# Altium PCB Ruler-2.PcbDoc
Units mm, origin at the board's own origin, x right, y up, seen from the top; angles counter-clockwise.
Board outline 100.08 x 35.05 mm, 2 copper layers (Top Layer, Bottom Layer); 25 components, 0 nets, 858 pads, 0 vias.
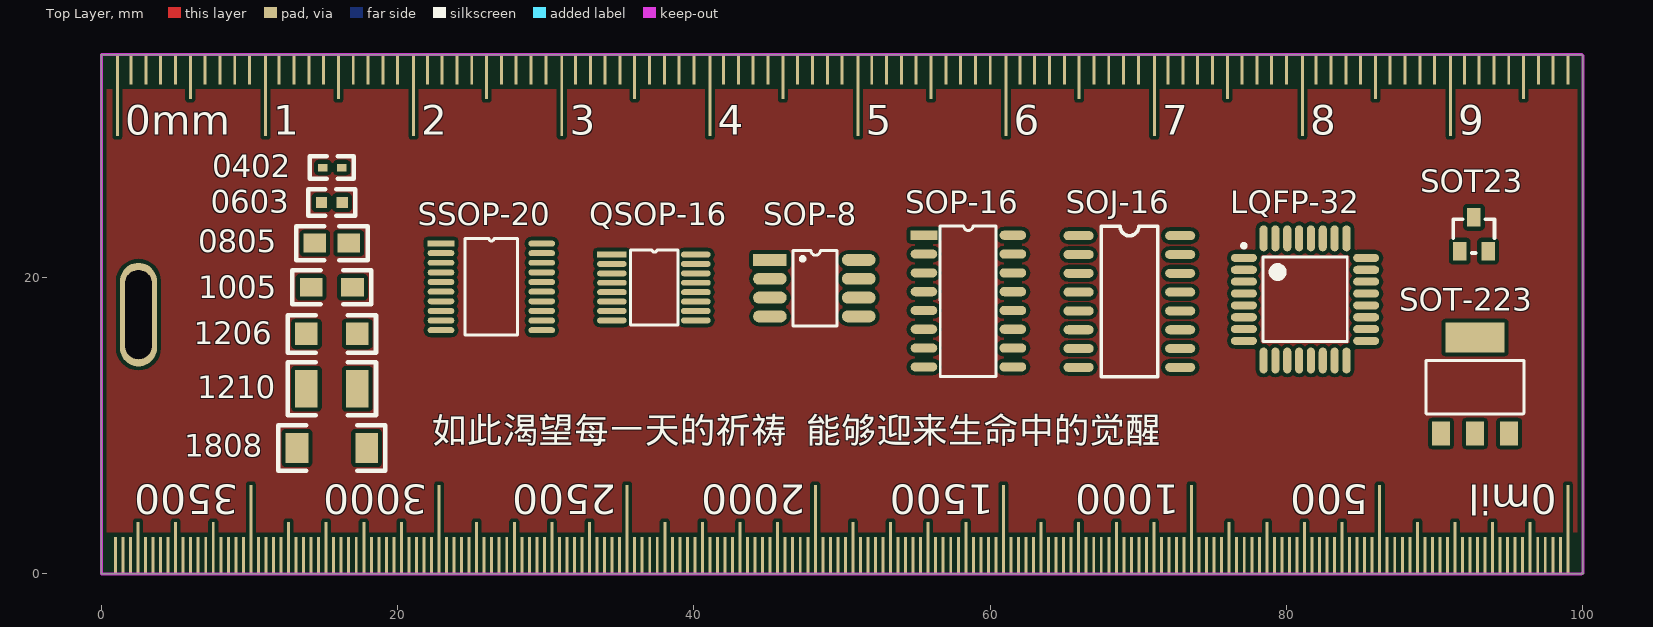
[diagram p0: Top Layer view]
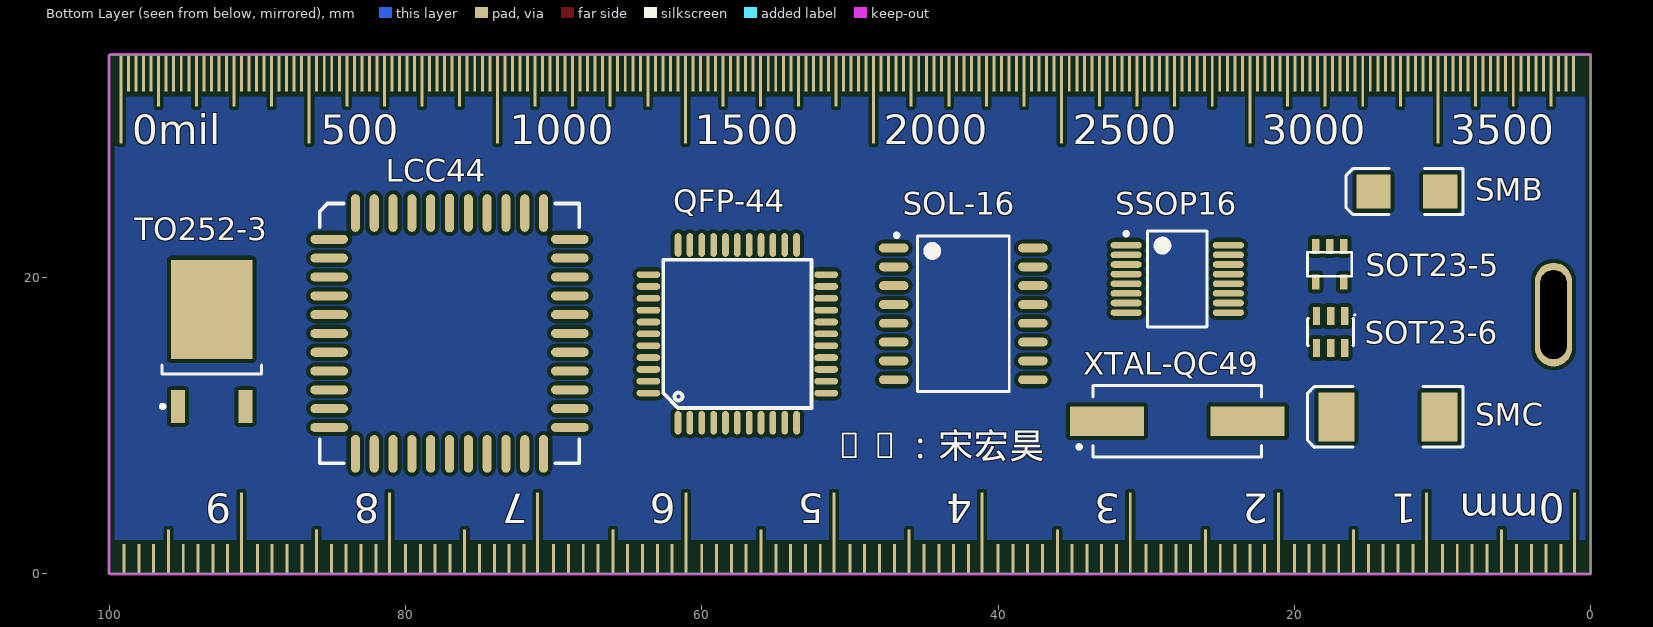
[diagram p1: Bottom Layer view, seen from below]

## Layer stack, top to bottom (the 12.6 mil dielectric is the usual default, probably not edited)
Top Solder: solder mask 0.0102, Solder Resist, Dk 3.5
Top Layer: signal copper 0.0356
Dielectric 1: dielectric 0.32, FR-4, Dk 4.8
Bottom Layer: signal copper 0.0356
Bottom Solder: solder mask 0.0102, Solder Resist, Dk 3.5

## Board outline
0,0 0,35.052 99.948,35.052 100,35 100,0.076 100.076,0

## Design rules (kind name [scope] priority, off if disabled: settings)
Clearance Clearance_1 [InPolygon] p1: gap=0.254 ignorepadtopadclearanceinfootprint=FALSE
Clearance [All] p2: gap=0.254 ignorepadtopadclearanceinfootprint=FALSE except(0: Arc-Hole Track-Hole SMDPad-Hole THPad-Hole Via-Hole Fill-Hole Poly-Hole Region-Hole Text-Hole)
PolygonConnect [All] p1: connectstyle=Relief reliefconductorwidth=0.254 reliefentries=4 polygonreliefangle="90 Angle" airgapwidth=0.254
RoutingVias [All] p1: holewidth=0.711 width=1.27 viastyle="Through Hole" minholewidth=0.711 minwidth=1.27 maxholewidth=0.711 maxwidth=1.27
SolderMaskExpansion [All] p1: expansion=0.102
Width [All] p1: maxlimit=0.254 minlimit=0.254 preferedwidth=0.254
30 further rules are at their usual default settings.

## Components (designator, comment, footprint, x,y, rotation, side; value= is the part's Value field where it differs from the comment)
0402 "0402" 0402 14.954,27.425 r0 top
0603 "0603" 0603 14.852,25.075 r0 top
0805 "0805" 0805 14.407,22.325 r0 top
1005 "1005" 1005 14.153,19.35 r0 top
1206 "1206" 1206 13.836,16.2 r0 top
1210 "1210" 1210 13.836,12.5 r0 top
1808 "1808" 1808 13.201,8.5 r0 top
LCC44 "LCC44" LCC44 77.028,24.358 r180 bottom
LQFP-32 "LQFP-32" LQFP-32 81.249,18.524 r0 top
QFP-44 "QFP-44" QFP-44 57.6,16.2 r180 bottom
QSOP-16 "QSOP-16" QSOP-16 34.46,21.554 r0 top
SMB "SMB" SMB 12.4,25.8 r0 bottom
SMC "SMC" SMC 13.675,10.6 r0 bottom
SOJ-16 "SOJ-16" SOJ-16 65.966,22.829 r0 top
SOL-16 "SOL-16" SOL-16_L 42.342,17.551 r180 bottom
SOP-8 "SOP-8" SOIC-8 45.124,21.189 r0 top
SOP-16 "SOP-16" SOP-16 55.524,22.859 r0 top
SOT23 "SOT23" SOT23 92.65,22.925 r0 top
SOT23-5 "SOT23-5" SOT23-5 16.661,22.1 r180 bottom
SOT23-6 "SOT23-6" SOT23-6 17.55,16.325 r180 bottom
SOT-223 "SOT-223" SOT-223 92.725,9.475 r0 top
SSOP16 "SSOP16" SSOP16_N 27.9,19.91 r180 bottom
SSOP-20 "SSOP-20" SSOP-20 22.924,22.299 r0 top
TO252-3 "TO252-3" TO-252AA_M 93.08,15.7 r90 bottom
XTAL-QC49 "XTAL-QC49" XTAL-QC49/SMD 27.9,10.3 r180 bottom

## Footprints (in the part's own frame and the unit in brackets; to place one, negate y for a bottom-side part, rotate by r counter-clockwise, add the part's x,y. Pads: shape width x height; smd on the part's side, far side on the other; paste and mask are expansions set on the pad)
0402 [mil]
  rect 25x20 smd: 1(0,0) 2(50,0)
  silkscreen extent -35,-30 82,30
0603 [mil]
  rect 30x30 smd: 1(0,0) 2(55,0)
  silkscreen extent -35,-35 90,35
0805 [mil]
  rect 60x50 smd: 1(0,0) 2(90,0)
  silkscreen extent -50,-45 140,45
1005 [mil]
  rect 60x50 smd: 1(0,0) 2(110,0)
  silkscreen extent -50,-45 160,45
1206 [mil]
  rect 60x60 smd: 1(0,0) 2(135,0)
  silkscreen extent -50,-50 185,50
1210 [mil]
  rect 60x100 smd: 1(0,0) 2(135,0)
  silkscreen extent -50,-70 185,70
1808 [mil]
  rect 60x80 smd: 1(0,0) 2(185,0)
  silkscreen extent -50,-60 235,60
LCC44 [mil]
  oct 24x100 smd: 1(0,0)
  oval 24x100 smd: 2(-50,0) 3(-100,0) 4(-150,0) 5(-200,0) 6(-250,0) 18(-250,-640) 19(-200,-640) 20(-150,-640) 21(-100,-640) 22(-50,-640) 23(0,-640) 24(50,-640) 25(100,-640) 26(150,-640) 27(200,-640) 28(250,-640) 40(250,0) 41(200,0) 42(150,0) 43(100,0) 44(50,0)
  oval 100x24 smd: 7(-320,-70) 8(-320,-120) 9(-320,-170) 10(-320,-220) 11(-320,-270) 12(-320,-320) 13(-320,-370) 14(-320,-420) 15(-320,-470) 16(-320,-520) 17(-320,-570) 29(320,-570) 30(320,-520) 31(320,-470) 32(320,-420) 33(320,-370) 34(320,-320) 35(320,-270) 36(320,-220) 37(320,-170) 38(320,-120) 39(320,-70)
  silkscreen extent -345,-665 345,25
LQFP-32 [mm] "TQFP, 32-Leads, Body 9.2x9.2mm (max), Pitch 0.80mm, IPC Medium Density"
  oval 1.75x0.55 smd: 1(-4.125,2.8) 2(-4.125,2) 3(-4.125,1.2) 4(-4.125,0.4) 5(-4.125,-0.4) 6(-4.125,-1.2) 7(-4.125,-2) 8(-4.125,-2.8) 17(4.125,-2.8) 18(4.125,-2) 19(4.125,-1.2) 20(4.125,-0.4) 21(4.125,0.4) 22(4.125,1.2) 23(4.125,2) 24(4.125,2.8)
  oval 0.55x1.75 smd: 9(-2.8,-4.125) 10(-2,-4.125) 11(-1.2,-4.125) 12(-0.4,-4.125) 13(0.4,-4.125) 14(1.2,-4.125) 15(2,-4.125) 16(2.8,-4.125) 25(2.8,4.125) 26(2,4.125) 27(1.2,4.125) 28(0.4,4.125) 29(-0.4,4.125) 30(-1.2,4.125) 31(-2,4.125) 32(-2.8,4.125)
  silkscreen extent -4.25,-2.85 2.85,3.75, body extent -3.5,-3.5 3.5,3.5, height 1.6
QFP-44 [mm]
  oval 0.45x1.6 smd: 1(-4,-6) 2(-3.2,-6) 3(-2.4,-6) 4(-1.6,-6) 5(-0.8,-6) 6(0,-6) 7(0.8,-6) 8(1.6,-6) 9(2.4,-6) 10(3.2,-6) 11(4,-6) 23(4,6) 24(3.2,6) 25(2.4,6) 26(1.6,6) 27(0.8,6) 28(0,6) 29(-0.8,6) 30(-1.6,6) 31(-2.4,6) 32(-3.2,6) 33(-4,6)
  oval 1.6x0.45 smd: 12(6,-4) 13(6,-3.2) 14(6,-2.4) 15(6,-1.6) 16(6,-0.8) 17(6,0) 18(6,0.8) 19(6,1.6) 20(6,2.4) 21(6,3.2) 22(6,4) 34(-6,4) 35(-6,3.2) 36(-6,2.4) 37(-6,1.6) 38(-6,0.8) 39(-6,0) 40(-6,-0.8) 41(-6,-1.6) 42(-6,-2.4) 43(-6,-3.2) 44(-6,-4)
  silkscreen extent -5,-5 5,5, body extent -6.01,-6 5.99,6, height 1.1
QSOP-16 [mm]
  rect 2x0.4 smd: 1(0,0)
  oval 2x0.4 smd: 2(0,-0.635) 3(0,-1.27) 4(0,-1.905) 5(0,-2.54) 6(0,-3.175) 7(0,-3.81) 8(0,-4.445) 9(5.664,-4.445) 10(5.664,-3.81) 11(5.664,-3.175) 12(5.664,-2.54) 13(5.664,-1.905) 14(5.664,-1.27) 15(5.664,-0.635) 16(5.664,0)
  silkscreen extent 1.25,-4.76 4.46,0.32
SMB [mm] "DO-214-AA/SMB; 2 C-Bend Leads; Body 5.3 x 3.6 mm, inc. leads (LxW)"
  rect 2.3x2.3 smd: 1(-2.25,0) 2(2.25,0)
  silkscreen extent -3.8,-1.55 4.1,1.55
SMC [mm] "DO-214-AB/SMC; 2 C-Bend Leads; Body 7.9 x 5.9 mm, inc. leads (LxW)"
  rect 2.4x3.3 smd: 1(-3.475,0) 2(3.475,0)
  silkscreen extent -5.07,-2.05 5.43,2.05
SOIC-8 [mm]
  rect 2.27x0.8 smd: 1(0,0)
  oval 2.27x0.8 smd: 2(0,-1.27) 3(0,-2.54) 4(0,-3.81) 5(6,-3.81) 6(6,-2.54) 7(6,-1.27) 8(6,0)
  silkscreen extent 1.55,-4.44 4.54,0.64
SOJ-16 [mil]
  oval 80x24 smd: 1(0,0) 2(0,-50) 3(0,-100) 4(0,-150) 5(0,-200) 6(0,-250) 7(0,-300) 8(0,-350) 9(270,-350) 10(270,-300) 11(270,-250) 12(270,-200) 13(270,-150) 14(270,-100) 15(270,-50) 16(270,0)
  silkscreen extent 60,-375 210,25
SOL-16_L [mm] "16-Pin Small Outline Integrated Circuit 1.27 mm Pitch, IPC High Density"
  oval 2x0.6 smd: 1(-4.7,4.445) 2(-4.7,3.175) 3(-4.7,1.905) 4(-4.7,0.635) 5(-4.7,-0.635) 6(-4.7,-1.905) 7(-4.7,-3.175) 8(-4.7,-4.445) 9(4.7,-4.445) 10(4.7,-3.175) 11(4.7,-1.905) 12(4.7,-0.635) 13(4.7,0.635) 14(4.7,1.905) 15(4.7,3.175) 16(4.7,4.445)
  silkscreen extent -4.62,-5.25 3.1,5.42, body extent -5.18,-5.14 5.12,5.16, height 2.65
SOP-16 [mm]
  rect 1.8x0.62 smd: 1(0,0)
  oval 1.8x0.62 smd: 2(0,-1.27) 3(0,-2.54) 4(0,-3.81) 5(0,-5.08) 6(0,-6.35) 7(0,-7.62) 8(0,-8.89) 9(6,-8.89) 10(6,-7.62) 11(6,-6.35) 12(6,-5.08) 13(6,-3.81) 14(6,-2.54) 15(6,-1.27) 16(6,0)
  silkscreen extent 1.09,-9.53 4.88,0.64
SOT23 [mil]
  rect 36x50 smd: B(-37.5,-45) C(0,45) E(37.5,-45)
  silkscreen extent -55,-50 55,40, body extent -57,-47 57,50, height 39
SOT23-5 [mm]
  rect 0.5x1 smd: 1(0,0) 2(-0.95,0) 3(-1.9,0) 4(-1.9,-2.4) 5(0,-2.4)
  silkscreen extent -2.45,-2 0.55,-0.4, body extent -2.4,-2.6 0.5,0.2, height 1.09
SOT23-6 [mm] "SOT-23/SC-74A; 5 Leads; Body 3.1 x 3 mm, inc. leads (LxW max)"
  rect 0.5x1.2 smd: 1(0.95,1.075) 2(0,1.075) 3(-0.95,1.075) 4(-0.95,-1.075) 5(0,-1.075) 6(0.95,-1.075)
  silkscreen extent -1.55,-0.9 1.65,1.15, body extent -1.4,-1.19 1.4,1.23, height 1.08
SOT-223 [mm]
  rect 1.2x1.6 smd: 1(-2.3,0) 2(0,0) 3(2.3,0)
  rect 4x2 smd: 4(0,6.477)
  silkscreen extent -3.3,1.32 3.3,4.93
SSOP16_N [mm] "SOP, 16-Leads, Body 6.2x5.3mm, Pitch 0.65mm, IPC Medium Density"
  oval 2.1x0.45 smd: 1(-3.45,2.275) 2(-3.45,1.625) 3(-3.45,0.975) 4(-3.45,0.325) 5(-3.45,-0.325) 6(-3.45,-0.975) 7(-3.45,-1.625) 8(-3.45,-2.275) 9(3.45,-2.275) 10(3.45,-1.625) 11(3.45,-0.975) 12(3.45,-0.325) 13(3.45,0.325) 14(3.45,0.975) 15(3.45,1.625) 16(3.45,2.275)
  silkscreen extent -3.57,-3.25 2,3.25, body extent -2.7,-3.25 2.7,3.25, height 2
SSOP-20 [mm]
  rect 1.8x0.4 smd: 1(0,0)
  oval 1.8x0.4 smd: 2(0,-0.65) 3(0,-1.3) 4(0,-1.95) 5(0,-2.6) 6(0,-3.25) 7(0,-3.9) 8(0,-4.55) 9(0,-5.2) 10(0,-5.85) 11(6.8,-5.85) 12(6.8,-5.2) 13(6.8,-4.55) 14(6.8,-3.9) 15(6.8,-3.25) 16(6.8,-2.6) 17(6.8,-1.95) 18(6.8,-1.3) 19(6.8,-0.65) 20(6.8,0)
  silkscreen extent 1.63,-6.18 5.16,0.32
TO-252AA_M [mm] "D-PAK, 4-Leads, Body 6.1x6.5mm, Pitch 2.28mm, Lead Span 9.8mm, IPC Low Density"
  rect 2.2x0.95 smd: 1(-4.4,2.28) 3(-4.4,-2.28)
  rect 6.7x5.5 smd: 4(2.15,0)
  silkscreen extent -4.52,-3.35 -1.6,3.43, body extent -4.9,-3.27 5.04,3.27, height 2.39
XTAL-QC49/SMD [mm]
  rect 5x2 smd: 1(-4.75,0) 2(4.75,0)
  silkscreen extent -6.75,-2.4 5.7,2.4, body extent -6.7,-2.46 6.7,2.44, height 4

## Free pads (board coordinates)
  oval 2.5x7 hole 1.8 slot 6 at 90 deg: 0(2.5,17.5)
  rect 0.2x5.5 smd far side: 1(1.075,2.752) 11(11.075,2.752) 21(21.075,2.752) 31(31.075,2.752) 41(41.075,2.752) 51(51.075,2.752) 61(61.075,2.752) 71(71.075,2.752) 81(81.075,2.752) 91(91.075,2.752)
  rect 0.2x5.5 smd: 1(1.075,32.3) 11(11.075,32.3) 21(21.075,32.3) 31(31.075,32.3) 41(41.075,32.3) 51(51.075,32.3) 61(61.075,32.3) 71(71.075,32.3) 81(81.075,32.3) 91(91.075,32.3)
  rect 0.2x2 smd far side: 2(2,1.002) 3(3,1.002) 4(4,1.002) 5(5,1.002) 7(7,1.002) 8(8,1.002) 9(9,1.002) 10(10,1.002) 12(12,1.002) 13(13,1.002) 14(14,1.002) 15(15,1.002) 17(17,1.002) 18(18,1.002) 19(19,1.002) 20(20,1.002) 22(22,1.002) 23(23,1.002) 24(24,1.002) 25(25,1.002) 27(27,1.002) 28(28,1.002) 29(29,1.002) 30(30,1.002) 32(32,1.002) 33(33,1.002) 34(34,1.002) 35(35,1.002) 37(37,1.002) 38(38,1.002) 39(39,1.002) 40(40,1.002) 42(42,1.002) 43(43,1.002) 44(44,1.002) 45(45,1.002) 47(47,1.002) 48(48,1.002) 49(49,1.002) 50(50,1.002) 52(52,1.002) 53(53,1.002) 54(54,1.002) 55(55,1.002) 57(57,1.002) 58(58,1.002) 59(59,1.002) 60(60,1.002) 62(62,1.002) 63(63,1.002) 64(64,1.002) 65(65,1.002) 67(67,1.002) 68(68,1.002) 69(69,1.002) 70(70,1.002) 72(72,1.002) 73(73,1.002) 74(74,1.002) 75(75,1.002) 77(77,1.002) 78(78,1.002) 79(79,1.002) 80(80,1.002) 82(82,1.002) 83(83,1.002) 84(84,1.002) 85(85,1.002) 87(87,1.002) 88(88,1.002) 89(89,1.002) 90(90,1.002) 92(92,1.002) 93(92,1.002) 94(93,1.002) 95(94,1.002) 96(95,1.002) 98(97,1.002) 99(98,1.002) 100(99,1.002)
  rect 0.2x2 smd: 2(2,34.05) 3(3,34.05) 4(4,34.05) 5(5,34.05) 7(7,34.05) 8(8,34.05) 9(9,34.05) 10(10,34.05) 12(12,34.05) 13(13,34.05) 14(14,34.05) 15(15,34.05) 17(17,34.05) 18(18,34.05) 19(19,34.05) 20(20,34.05) 22(22,34.05) 23(23,34.05) 24(24,34.05) 25(25,34.05) 27(27,34.05) 28(28,34.05) 29(29,34.05) 30(30,34.05) 32(32,34.05) 33(33,34.05) 34(34,34.05) 35(35,34.05) 37(37,34.05) 38(38,34.05) 39(39,34.05) 40(40,34.05) 42(42,34.05) 43(43,34.05) 44(44,34.05) 45(45,34.05) 47(47,34.05) 48(48,34.05) 49(49,34.05) 50(50,34.05) 52(52,34.05) 53(53,34.05) 54(54,34.05) 55(55,34.05) 57(57,34.05) 58(58,34.05) 59(59,34.05) 60(60,34.05) 62(62,34.05) 63(63,34.05) 64(64,34.05) 65(65,34.05) 67(67,34.05) 68(68,34.05) 69(69,34.05) 70(70,34.05) 72(72,34.05) 73(73,34.05) 74(74,34.05) 75(75,34.05) 77(77,34.05) 78(78,34.05) 79(79,34.05) 80(80,34.05) 82(82,34.05) 83(83,34.05) 84(84,34.05) 85(85,34.05) 87(87,34.05) 88(88,34.05) 89(89,34.05) 90(90,34.05) 92(92,34.05) 93(92,34.05) 94(93,34.05) 95(94,34.05) 96(95,34.05) 98(97,34.05) 99(98,34.05) 100(99,34.05)
  rect 0.2x3 smd far side: 6(6,1.502) 16(16,1.502) 26(26,1.502) 36(36,1.502) 46(46,1.502) 56(56,1.502) 66(66,1.502) 76(76,1.502) 86(86,1.502) 97(96,1.502)
  rect 0.2x3 smd: 6(6,33.55) 16(16,33.55) 26(26,33.55) 36(36,33.55) 46(46,33.55) 56(56,33.55) 66(66,33.55) 76(76,33.55) 86(86,33.55) 97(96,33.55)
  rect 0.2x6 smd: 102(98.99,3.002) 129(86.29,3.002) 154(73.59,3.002) 179(60.89,3.002) 204(48.19,3.002) 229(35.49,3.002) 254(22.79,3.002) 279(10.09,3.002)
  rect 0.2x6 smd far side: 102(99.2,32.05) 129(86.5,32.05) 154(73.8,32.05) 179(61.1,32.05) 204(48.4,32.05) 229(35.7,32.05) 254(23,32.05) 279(10.3,32.05)
  rect 0.2x2.5 smd: 103(98.482,1.252) 104(97.974,1.252) 107(97.466,1.252) 108(96.958,1.252) 110(95.942,1.252) 111(95.434,1.252) 112(94.926,1.252) 113(94.418,1.252) 115(93.402,1.252) 116(92.894,1.252) 117(92.386,1.252) 118(91.878,1.252) 120(90.862,1.252) 121(90.354,1.252) 122(89.846,1.252) 123(89.338,1.252) 125(88.322,1.252) 126(87.814,1.252) 127(87.306,1.252) 128(86.798,1.252) 130(85.782,1.252) 131(85.274,1.252) 132(84.766,1.252) 133(84.258,1.252) 135(83.242,1.252) 136(82.734,1.252) 137(82.226,1.252) 138(81.718,1.252) 140(80.702,1.252) 141(80.194,1.252) 142(79.686,1.252) 143(79.178,1.252) 145(78.162,1.252) 146(77.654,1.252) 147(77.146,1.252) 148(76.638,1.252) 150(75.622,1.252) 151(75.114,1.252) 152(74.606,1.252) 153(74.098,1.252) 155(73.082,1.252) 156(72.574,1.252) 157(72.066,1.252) 158(71.558,1.252) 160(70.542,1.252) 161(70.034,1.252) 162(69.526,1.252) 163(69.018,1.252) 165(68.002,1.252) 166(67.494,1.252) 167(66.986,1.252) 168(66.478,1.252) 170(65.462,1.252) 171(64.954,1.252) 172(64.446,1.252) 173(63.938,1.252) 175(62.922,1.252) 176(62.414,1.252) 177(61.906,1.252) 178(61.398,1.252) 180(60.382,1.252) 181(59.874,1.252) 182(59.366,1.252) 183(58.858,1.252) 185(57.842,1.252) 186(57.334,1.252) 187(56.826,1.252) 188(56.318,1.252) 190(55.302,1.252) 191(54.794,1.252) 192(54.286,1.252) 193(53.778,1.252) 195(52.762,1.252) 196(52.254,1.252) 197(51.746,1.252) 198(51.238,1.252) 200(50.222,1.252) 201(49.714,1.252) 202(49.206,1.252) 203(48.698,1.252) 205(47.682,1.252) 206(47.174,1.252) 207(46.666,1.252) 208(46.158,1.252) 210(45.142,1.252) 211(44.634,1.252) 212(44.126,1.252) 213(43.618,1.252) 215(42.602,1.252) 216(42.094,1.252) 217(41.586,1.252) 218(41.078,1.252) 220(40.062,1.252) 221(39.554,1.252) 222(39.046,1.252) 223(38.538,1.252) 225(37.522,1.252) 226(37.014,1.252) 227(36.506,1.252) 228(35.998,1.252) 230(34.982,1.252) 231(34.474,1.252) 232(33.966,1.252) 233(33.458,1.252) 235(32.442,1.252) 236(31.934,1.252) 237(31.426,1.252) 238(30.918,1.252) 240(29.902,1.252) 241(29.394,1.252) 242(28.886,1.252) 243(28.378,1.252) 245(27.362,1.252) 246(26.854,1.252) 247(26.346,1.252) 248(25.838,1.252) 250(24.822,1.252) 251(24.314,1.252) 252(23.806,1.252) 253(23.298,1.252) 255(22.282,1.252) 256(21.774,1.252) 257(21.266,1.252) 258(20.758,1.252) 260(19.742,1.252) 261(19.234,1.252) 262(18.726,1.252) 263(18.218,1.252) 265(17.202,1.252) 266(16.694,1.252) 267(16.186,1.252) 268(15.678,1.252) 270(14.662,1.252) 271(14.154,1.252) 272(13.646,1.252) 273(13.138,1.252) 275(12.122,1.252) 276(11.614,1.252) 277(11.106,1.252) 278(10.598,1.252) 280(9.582,1.252) 281(9.074,1.252) 282(8.566,1.252) 283(8.058,1.252) 285(7.042,1.252) 286(6.534,1.252) 287(6.026,1.252) 288(5.518,1.252) 290(4.502,1.252) 291(3.994,1.252) 292(3.486,1.252) 293(2.978,1.252) 295(1.962,1.252) 296(1.454,1.252) 297(0.946,1.252)
  rect 0.2x2.5 smd far side: 103(98.692,33.8) 104(98.184,33.8) 107(97.676,33.8) 108(97.168,33.8) 110(96.152,33.8) 111(95.644,33.8) 112(95.136,33.8) 113(94.628,33.8) 115(93.612,33.8) 116(93.104,33.8) 117(92.596,33.8) 118(92.088,33.8) 120(91.072,33.8) 121(90.564,33.8) 122(90.056,33.8) 123(89.548,33.8) 125(88.532,33.8) 126(88.024,33.8) 127(87.516,33.8) 128(87.008,33.8) 130(85.992,33.8) 131(85.484,33.8) 132(84.976,33.8) 133(84.468,33.8) 135(83.452,33.8) 136(82.944,33.8) 137(82.436,33.8) 138(81.928,33.8) 140(80.912,33.8) 141(80.404,33.8) 142(79.896,33.8) 143(79.388,33.8) 145(78.372,33.8) 146(77.864,33.8) 147(77.356,33.8) 148(76.848,33.8) 150(75.832,33.8) 151(75.324,33.8) 152(74.816,33.8) 153(74.308,33.8) 155(73.292,33.8) 156(72.784,33.8) 157(72.276,33.8) 158(71.768,33.8) 160(70.752,33.8) 161(70.244,33.8) 162(69.736,33.8) 163(69.228,33.8) 165(68.212,33.8) 166(67.704,33.8) 167(67.196,33.8) 168(66.688,33.8) 170(65.672,33.8) 171(65.164,33.8) 172(64.656,33.8) 173(64.148,33.8) 175(63.132,33.8) 176(62.624,33.8) 177(62.116,33.8) 178(61.608,33.8) 180(60.592,33.8) 181(60.084,33.8) 182(59.576,33.8) 183(59.068,33.8) 185(58.052,33.8) 186(57.544,33.8) 187(57.036,33.8) 188(56.528,33.8) 190(55.512,33.8) 191(55.004,33.8) 192(54.496,33.8) 193(53.988,33.8) 195(52.972,33.8) 196(52.464,33.8) 197(51.956,33.8) 198(51.448,33.8) 200(50.432,33.8) 201(49.924,33.8) 202(49.416,33.8) 203(48.908,33.8) 205(47.892,33.8) 206(47.384,33.8) 207(46.876,33.8) 208(46.368,33.8) 210(45.352,33.8) 211(44.844,33.8) 212(44.336,33.8) 213(43.828,33.8) 215(42.812,33.8) 216(42.304,33.8) 217(41.796,33.8) 218(41.288,33.8) 220(40.272,33.8) 221(39.764,33.8) 222(39.256,33.8) 223(38.748,33.8) 225(37.732,33.8) 226(37.224,33.8) 227(36.716,33.8) 228(36.208,33.8) 230(35.192,33.8) 231(34.684,33.8) 232(34.176,33.8) 233(33.668,33.8) 235(32.652,33.8) 236(32.144,33.8) 237(31.636,33.8) 238(31.128,33.8) 240(30.112,33.8) 241(29.604,33.8) 242(29.096,33.8) 243(28.588,33.8) 245(27.572,33.8) 246(27.064,33.8) 247(26.556,33.8) 248(26.048,33.8) 250(25.032,33.8) 251(24.524,33.8) 252(24.016,33.8) 253(23.508,33.8) 255(22.492,33.8) 256(21.984,33.8) 257(21.476,33.8) 258(20.968,33.8) 260(19.952,33.8) 261(19.444,33.8) 262(18.936,33.8) 263(18.428,33.8) 265(17.412,33.8) 266(16.904,33.8) 267(16.396,33.8) 268(15.888,33.8) 270(14.872,33.8) 271(14.364,33.8) 272(13.856,33.8) 273(13.348,33.8) 275(12.332,33.8) 276(11.824,33.8) 277(11.316,33.8) 278(10.808,33.8) 280(9.792,33.8) 281(9.284,33.8) 282(8.776,33.8) 283(8.268,33.8) 285(7.252,33.8) 286(6.744,33.8) 287(6.236,33.8) 288(5.728,33.8) 290(4.712,33.8) 291(4.204,33.8) 292(3.696,33.8) 293(3.188,33.8) 295(2.172,33.8) 296(1.664,33.8) 297(1.156,33.8)
  rect 0.2x3.5 smd: 109(96.45,1.752) 114(93.91,1.752) 119(91.37,1.752) 124(88.83,1.752) 134(83.75,1.752) 139(81.21,1.752) 144(78.67,1.752) 149(76.13,1.752) 159(71.05,1.752) 164(68.51,1.752) 169(65.97,1.752) 174(63.43,1.752) 184(58.35,1.752) 189(55.81,1.752) 194(53.27,1.752) 199(50.73,1.752) 209(45.65,1.752) 214(43.11,1.752) 219(40.57,1.752) 224(38.03,1.752) 234(32.95,1.752) 239(30.41,1.752) 244(27.87,1.752) 249(25.33,1.752) 259(20.25,1.752) 264(17.71,1.752) 269(15.17,1.752) 274(12.63,1.752) 284(7.55,1.752) 289(5.01,1.752) 294(2.47,1.752)
  rect 0.2x3.5 smd far side: 109(96.66,33.3) 114(94.12,33.3) 119(91.58,33.3) 124(89.04,33.3) 134(83.96,33.3) 139(81.42,33.3) 144(78.88,33.3) 149(76.34,33.3) 159(71.26,33.3) 164(68.72,33.3) 169(66.18,33.3) 174(63.64,33.3) 184(58.56,33.3) 189(56.02,33.3) 194(53.48,33.3) 199(50.94,33.3) 209(45.86,33.3) 214(43.32,33.3) 219(40.78,33.3) 224(38.24,33.3) 234(33.16,33.3) 239(30.62,33.3) 244(28.08,33.3) 249(25.54,33.3) 259(20.46,33.3) 264(17.92,33.3) 269(15.38,33.3) 274(12.84,33.3) 284(7.76,33.3) 289(5.22,33.3) 294(2.68,33.3)

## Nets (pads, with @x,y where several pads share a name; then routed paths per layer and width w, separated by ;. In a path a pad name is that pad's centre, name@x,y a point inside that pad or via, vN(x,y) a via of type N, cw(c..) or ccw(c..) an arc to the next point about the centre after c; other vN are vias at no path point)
pads on no net: 0402.1 0402.2 0603.1 0603.2 0805.1 0805.2 1005.1 1005.2 1206.1 1206.2 1210.1 1210.2 1808.1 1808.2 LCC44.1 LCC44.2 LCC44.3 LCC44.4 LCC44.5 LCC44.6 LCC44.7 LCC44.8 LCC44.9 LCC44.10 LCC44.11 LCC44.12 LCC44.13 LCC44.14 LCC44.15 LCC44.16 LCC44.17 LCC44.18 LCC44.19 LCC44.20 LCC44.21 LCC44.22 LCC44.23 LCC44.24 LCC44.25 LCC44.26 LCC44.27 LCC44.28 LCC44.29 LCC44.30 LCC44.31 LCC44.32 LCC44.33 LCC44.34 LCC44.35 LCC44.36 LCC44.37 LCC44.38 LCC44.39 LCC44.40 LCC44.41 LCC44.42 LCC44.43 LCC44.44 LQFP-32.1 LQFP-32.2 LQFP-32.3 LQFP-32.4 LQFP-32.5 LQFP-32.6 LQFP-32.7 LQFP-32.8 LQFP-32.9 LQFP-32.10 LQFP-32.11 LQFP-32.12 LQFP-32.13 LQFP-32.14 LQFP-32.15 LQFP-32.16 LQFP-32.17 LQFP-32.18 LQFP-32.19 LQFP-32.20 LQFP-32.21 LQFP-32.22 LQFP-32.23 LQFP-32.24 LQFP-32.25 LQFP-32.26 LQFP-32.27 LQFP-32.28 LQFP-32.29 LQFP-32.30 LQFP-32.31 LQFP-32.32 QFP-44.1 QFP-44.2 QFP-44.3 QFP-44.4 QFP-44.5 QFP-44.6 QFP-44.7 QFP-44.8 QFP-44.9 QFP-44.10 QFP-44.11 QFP-44.12 QFP-44.13 QFP-44.14 QFP-44.15 QFP-44.16 QFP-44.17 QFP-44.18 QFP-44.19 QFP-44.20 QFP-44.21 QFP-44.22 QFP-44.23 QFP-44.24 QFP-44.25 QFP-44.26 QFP-44.27 QFP-44.28 QFP-44.29 QFP-44.30 QFP-44.31 QFP-44.32 QFP-44.33 QFP-44.34 QFP-44.35 QFP-44.36 QFP-44.37 QFP-44.38 QFP-44.39 QFP-44.40 QFP-44.41 QFP-44.42 QFP-44.43 QFP-44.44 QSOP-16.1 QSOP-16.2 QSOP-16.3 QSOP-16.4 QSOP-16.5 QSOP-16.6 QSOP-16.7 QSOP-16.8 QSOP-16.9 QSOP-16.10 QSOP-16.11 QSOP-16.12 QSOP-16.13 QSOP-16.14 QSOP-16.15 QSOP-16.16 SMB.1 SMB.2 SMC.1 SMC.2 SOJ-16.1 SOJ-16.2 SOJ-16.3 SOJ-16.4 SOJ-16.5 SOJ-16.6 SOJ-16.7 SOJ-16.8 SOJ-16.9 SOJ-16.10 SOJ-16.11 SOJ-16.12 SOJ-16.13 SOJ-16.14 SOJ-16.15 SOJ-16.16 SOL-16.1 SOL-16.2 SOL-16.3 SOL-16.4 SOL-16.5 SOL-16.6 SOL-16.7 SOL-16.8 SOL-16.9 SOL-16.10 SOL-16.11 SOL-16.12 SOL-16.13 SOL-16.14 SOL-16.15 SOL-16.16 SOP-8.1 SOP-8.2 SOP-8.3 SOP-8.4 SOP-8.5 SOP-8.6 SOP-8.7 SOP-8.8 SOP-16.1 SOP-16.2 SOP-16.3 SOP-16.4 SOP-16.5 SOP-16.6 SOP-16.7 SOP-16.8 SOP-16.9 SOP-16.10 SOP-16.11 SOP-16.12 SOP-16.13 SOP-16.14 SOP-16.15 SOP-16.16 SOT23-5.1 SOT23-5.2 SOT23-5.3 SOT23-5.4 SOT23-5.5 SOT23-6.1 SOT23-6.2 SOT23-6.3 SOT23-6.4 SOT23-6.5 SOT23-6.6 SOT23.B SOT23.C SOT23.E SOT-223.1 SOT-223.2 SOT-223.3 SOT-223.4 SSOP16.1 SSOP16.2 SSOP16.3 SSOP16.4 SSOP16.5 SSOP16.6 SSOP16.7 SSOP16.8 SSOP16.9 SSOP16.10 SSOP16.11 SSOP16.12 SSOP16.13 SSOP16.14 SSOP16.15 SSOP16.16 SSOP-20.1 SSOP-20.2 SSOP-20.3 SSOP-20.4 SSOP-20.5 SSOP-20.6 SSOP-20.7 SSOP-20.8 SSOP-20.9 SSOP-20.10 SSOP-20.11 SSOP-20.12 SSOP-20.13 SSOP-20.14 SSOP-20.15 SSOP-20.16 SSOP-20.17 SSOP-20.18 SSOP-20.19 SSOP-20.20 TO252-3.1 TO252-3.3 TO252-3.4 XTAL-QC49.1 XTAL-QC49.2

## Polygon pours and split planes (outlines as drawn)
no net on Top Layer "Top Layer-No Net" (solid, pour order 0): -0.238,32.715 100.076,32.715 100.076,2.819 -0.021,2.819
no net on Bottom Layer "Top Layer-No Net" (solid, pour order 2): 0,32.207 100,32.207 100,2.286 0,2.286

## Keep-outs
Keep-Out Layer:
  lines w0.2: 0,0 99.924,0 100,0.076 100,35 99.948,35.052 0,35.052 0,0

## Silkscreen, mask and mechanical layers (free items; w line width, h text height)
Top Overlay:
  text "0mm" at 1.6,29.65 h2
  text "1" at 11.6,29.65 h2
  text "2" at 21.6,29.65 h2
  text "3" at 31.6,29.65 h2
  text "4" at 41.6,29.65 h2
  text "5" at 51.6,29.65 h2
  text "6" at 61.6,29.65 h2
  text "7" at 71.6,29.65 h2
  text "8" at 81.6,29.65 h2
  text "9" at 91.6,29.65 h2
  text "如此渴望每一天的祈祷  能够迎来生命中的觉醒" at 22.301,8.28 h3
  text "3500" at 9.25,6 h2 r180
  text "3000" at 22,6 h2 r180
  text "2500" at 34.75,6 h2 r180
  text "2000" at 47.5,6 h2 r180
  text "1500" at 60.25,6 h2 r180
  text "1000" at 72.75,6 h2 r180
  text "500" at 85.5,6 h2 r180
  text "0mil" at 98.25,6 h2 r180
Bottom Overlay:
  text "3500" at 9.46,29.002 h2
  text "3000" at 22.21,29.002 h2
  text "2500" at 34.96,29.002 h2
  text "2000" at 47.71,29.002 h2
  text "1500" at 60.46,29.002 h2
  text "1000" at 72.96,29.002 h2
  text "500" at 85.71,29.002 h2
  text "0mil" at 98.46,29.002 h2
  text "By：宋宏昊" at 51.232,7.239 h3
  text "0mm" at 1.75,5.4 h2 r180
  text "1" at 11.75,5.4 h2 r180
  text "2" at 21.75,5.4 h2 r180
  text "3" at 31.75,5.4 h2 r180
  text "4" at 41.75,5.4 h2 r180
  text "5" at 51.75,5.4 h2 r180
  text "6" at 61.75,5.4 h2 r180
  text "7" at 71.75,5.4 h2 r180
  text "8" at 81.75,5.4 h2 r180
  text "9" at 91.75,5.4 h2 r180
